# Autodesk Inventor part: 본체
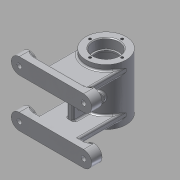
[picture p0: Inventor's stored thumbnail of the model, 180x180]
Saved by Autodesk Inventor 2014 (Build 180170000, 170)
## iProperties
Created: 2015-11
Part Number: 본체
Material: 알루미늄 6061
Document SubType Name: Modeling
Designer: L10
Density: 2.71 g/cm^3
Appearance: 알루미늄 - 평지
Mass: 358.802 g
Surface Area: 460.446 cm^2
Volume: 132.399 cm^3
Author: L10
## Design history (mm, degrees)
sketch "스케치1"
  geometry: L1 (0, 35)-(0, -35); L2 (25, -35)-(25, 0); L3 (25, -35)-(16, -35); L4 (16, -35)-(16, -23); L5 (16, -23)-(14, -23); L6 (14, -23)-(14, -21); L7 (14, -21)-(21, -21); L8 (21, -21)-(21, 0); L9 (21, 0)-(25, 0); 3 further points
  constraints: 18 end point, 4 parallel, 4 perpendicular, 2 midpoint, 1 coincident, 1 horizontal alignment, 1 vertical
  dimensions: "d0" = 70 distance of L1.start L1.end; "d1" = 50 diameter of L2 L1; "d2" = 32 diameter of L4 L1; "d3" = 28 diameter of L6 L1; "d4" = 42 diameter of L8 L1; "d5" = 2 distance of L5.end L6.end; "d6" = 12 distance of L3.end L4.end; "d7" = 35 distance of L2.start L2.end
revolve "회전1" sketch "스케치1" stored, may be unused: angle "d8" = 90 deg
node "작업 평면2"
sketch "스케치2"
  geometry: L1 (-25, 0)-(25, 0); L2 (25, 0)-(25, -68); L3 (25, -68)-(-25, -68); L4 (-25, -68)-(-25, 0); C1 r 25 at (0, 0) reference; A1 r 25 centre (0, 0) between (-25, 0) and (25, 0); 3 further points
  constraints: 8 end point, 2 coincident, 2 midpoint, 2 parallel, 2 point on circle, 1 centre point, 1 horizontal, 1 perpendicular, 1 vertical alignment
  dimensions: "d11" = 68 distance from line of L3 point (0, 0); "d12" = 50 distance of L2.end L3.end
extrude "돌출1" join sketch "스케치2" distance "d13" = 8; taper "d14" = 0 deg
sketch "스케치3"
  geometry: L1 (0, 0)-(50, 0) reference; L2 (50, 0)-(50, 8) reference; L3 (0, 8)-(50, 8) reference; L4 (0, 0)-(0, 8) reference; L5 (-15, 8)-(65, 8); L6 (65, 8)-(65, -12); L7 (65, -12)-(-15, -12); L8 (-15, -12)-(-15, 8); 6 further points
  constraints: 8 end point, 5 midpoint, 2 coincident, 2 parallel, 2 vertical alignment, 1 horizontal, 1 perpendicular, 4 other
  dimensions: "d15" = 80 distance of L5.start L5.end; "d16" = 20 distance of L7.end L5.start
extrude "돌출2" join sketch "스케치3" distance "d17" = 10; taper "d18" = 0 deg
extrude "돌출3" join sketch "스케치3" distance "d19" = 13; taper "d20" = 0 deg
hole "구멍1" diameter "d23" = 6; stored, may be unused: countersink angle "d27" = 90 deg, drill point angle "d29" = 118 deg; dims "d21" = 10, "d22" = 10, "d24" = 6, "d25" = 12, "d26" = 4, "d28" = 13
chamfer "모따기1" distance "d30" = 1; stored, may be unused: second distance "d31" = 2, angle "d32" = 45 deg
sketch "스케치4"
  geometry: L1 (-25, -20)-(-45, -20); L2 (-45, -20)-(-45, 20); L3 (-45, 20)-(-25, 20); L4 (-25, 20)-(-25, -20); L5 (0, 20)-(-58, 20) reference; L6 (0, -20)-(-58, -20) reference; L7 (-25, 35)-(-25, -35) reference; L8 (-31.5, 8)-(-38.5, 8); L9 (-38.5, 8)-(-38.5, -8); L10 (-38.5, -8)-(-31.5, -8); L11 (-31.5, -8)-(-31.5, 8); C1 r 3.5 at (-35, -8); 6 further points
  constraints: 16 end point, 7 midpoint, 4 parallel, 2 horizontal, 2 horizontal alignment, 2 perpendicular, 1 centre point, 1 point on line, 1 tangent, 1 vertical alignment, 2 other
  dimensions: "d34" = 20 distance between parallel lines of L2 L7; "d36" = 23 dimension on C1; "d38" = 3.5 radius of C1
extrude "돌출4" join sketch "스케치4" stored distance "d39" = 8; taper "d40" = 0 deg
node "작업 평면4"
sketch "스케치6"
  geometry: C1 r 5 at (0, 0); 1 further point
  constraints: 1 centre point, 1 coincident
  dimensions: "d45" = 10 diameter of C1
extrude "돌출6" join sketch "스케치6" stored distance "d46" = 28; taper "d47" = 0 deg
hole "구멍2" diameter "d50" = 5.188; stored, may be unused: countersink angle "d54" = 90 deg, drill point angle "d56" = 0 deg; dims "d48" = 10, "d49" = 10, "d51" = 6, "d52" = 12, "d53" = 4, "d55" = 13
sketch "스케치7"
  geometry: L1 (0, 0)-(14, -24.249); L2 (0, 47.2)-(0, -87.2) reference; L3 (14, -24.249)-(19.196, -21.249); L4 (19.196, -21.249)-(17.331, -18.018); L5 (14, -24.249)-(12.5, -21.651); A1 r 25 centre (0, 0) between (0, -25) and (25, 0) reference
  constraints: 8 end point, 2 perpendicular, 2 point on circle, 1 point on line
  dimensions: "d57" = 30 deg angle of L1 L2; "d58" = 28 distance of L1.start L1.end; "d59" = 12 diameter of L4 L1
revolve "회전2" sketch "스케치7" stored, may be unused: angle "d60" = 90 deg
hole "구멍3" diameter "d63" = 5.188; stored, may be unused: countersink angle "d67" = 90 deg, drill point angle "d69" = 0 deg; dims "d61" = 10, "d62" = 10, "d64" = 6, "d65" = 12, "d66" = 4, "d68" = 13
sketch "스케치8"
  geometry: L1 (0, 0)-(0, 40) reference; L2 (4, 0)-(0, 0) reference; L3 (4, 40)-(4, 0) reference; L4 (0, 40)-(4, 40) reference; L5 (4, 0)-(4, 40) reference; L6 (-4, 0)-(4, 0) reference; L7 (-4, 40)-(-4, 0) reference; L8 (4, 40)-(-4, 40) reference; L9 (-4, 40)-(4, 40); L10 (4, 40)-(4, 0); L11 (4, 0)-(-4, 0); L12 (-4, 0)-(-4, 40); 1 further point
  constraints: 8 end point, 2 parallel, 1 horizontal, 1 perpendicular
extrude "돌출7" join sketch "스케치8" stored distance "d75" = 28; taper "d76" = 0 deg
fillet "모깎기1" dims "d70" = 0.3, "d71" = 0.3
fillet "모깎기2" dims "d72" = 3
fillet "모깎기3" dims "d73" = 2
fillet "모깎기4" dims "d74" = 2
fillet "모깎기5" dims "d77" = 2
chamfer "모따기6" distance "d90" = 1; stored, may be unused: second distance "d91" = 2, angle "d92" = 45 deg
chamfer "모따기7" distance "d93" = 1; stored, may be unused: second distance "d94" = 2, angle "d95" = 45 deg
sketch "스케치9" dims "d96" = 40
  geometry: C1 r 25 at (0, 0) reference; C2 r 17 at (0, 0) reference; 2 further points
  constraints: 2 vertical alignment, 1 coincident, 2 other
hole "구멍4" sketch "스케치9" at (0, 20) diameter "d97" = 3.242; stored, may be unused: countersink angle "d101" = 90 deg, drill point angle "d103" = 118 deg; dims "d98" = 8, "d99" = 12, "d100" = 4, "d102" = 10
chamfer "모따기8" distance "d107" = 1; stored, may be unused: second distance "d108" = 2, angle "d109" = 45 deg
chamfer "모따기9" distance "d110" = 1; stored, may be unused: second distance "d111" = 2, angle "d112" = 45 deg
node "작업 평면5"
sketch "스케치11"
  geometry: L1 (25, 35)-(25, -35) reference; 2 further points
  constraints: 1 horizontal alignment, 1 midpoint
node "작업 평면6"
sketch "스케치12"
  geometry: L1 (-25, 35)-(-25, -35) reference; L2 (-25, -35)-(25, -35) reference; 2 further points
  constraints: 1 other
  dimensions: "d114" = 25 distance from line of point (0, 0) L1; "d115" = 35 distance from line of L2 point (0, 0)
feature "엠보싱1" sketch "스케치12" dims "d11" = 68, "d12" = 50, "d116" = 0.5, "d117" = 0
chamfer "모따기10" distance "d118" = 1; stored, may be unused: second distance "d119" = 2, angle "d120" = 45 deg
chamfer "모따기11" distance "d121" = 1; stored, may be unused: second distance "d122" = 2, angle "d123" = 45 deg
chamfer "모따기12" distance "d124" = 1; stored, may be unused: second distance "d125" = 2, angle "d126" = 45 deg
node "솔리드1"
mirror "대칭1"
mirror "대칭2"
pattern_circular "원형 패턴1" dims angle "d105" = 360 deg
mirror "대칭3"
node "투영된 루프1"
other parameters: "d10" = -28, "d44" = 28, "d113" = -25
